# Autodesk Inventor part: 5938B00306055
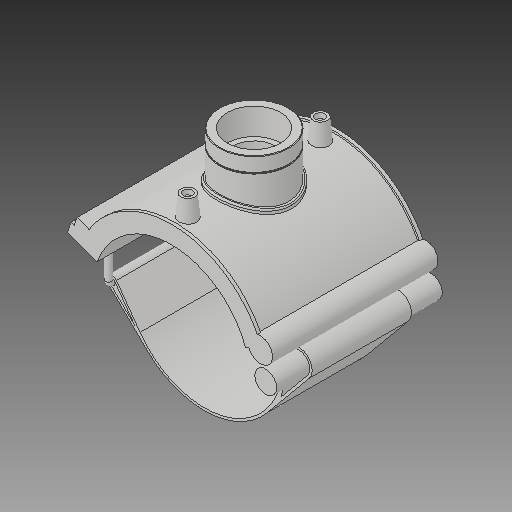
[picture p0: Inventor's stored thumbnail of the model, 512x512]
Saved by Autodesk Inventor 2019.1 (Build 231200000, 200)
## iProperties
Created: 2017-07
Part Number: 5938B00306055
Material: Generic
Description: PLASSON TRANSITION SADDLE 6''IPS x 2"NPT
Document SubType Name: Modeling
Designer: KIM
Density: 1 g/cm^3
Appearance: Default
Author: KIM
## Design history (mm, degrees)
derived "5938B.ipt"
feature "Solid1::5938B.ipt"
tag "TaggingFeature1"
body "Solid1"
other parameters: "d_" = 168, "B_" = 173.736, "H_" = 46.736, "L_" = 176.022, "d_t" = 6, "G_" = 56.656, "d148" = 2.52, "d160" = 2.52, "d169" = 2.52, "d192" = 6.72, "d0" = 168, "d1" = 201.6, "d2" = 434.34, "d3" = 42, "d4" = 176.022, "d5" = 0, "d40" = 104.832, "d41" = 79.3184, "d43" = 0, "d45" = 0, "d47" = 147.536, "d48" = 73.6528, "d50" = 0, "d78" = 122.8, "d79" = 15, "d80" = 70.4088, "d82" = 5 deg, "d84" = 4, "d85" = 14, "d86" = 0, "d87" = 3, "d88" = 0, "d96" = 205.632, "d97" = 3.52044, "d98" = 0, "d102" = 1.69968, "d103" = 56.656, "d104" = 28.0416, "d105" = 0, "d106" = 45.3248, "d108" = 0, "d109" = -15.57867, "d111" = 0.5, "d112" = 0.5, "d113" = 0, "d114" = 0.5, "d117" = 0.56656, "d120" = 140 deg, "d121" = 24.228, "d122" = 20 deg, "d123" = 806.4, "d124" = 120.96, "d126" = 0, "d143" = 173.04, "d145" = 25.84615, "d149" = 2.52, "d150" = 28.43077, "d153" = 176.022, "d154" = 0, "d156" = 100.8, "d157" = 160 deg, "d159" = 6.72, "d161" = 2.52, "d162" = 105.6132, "d163" = 0, "d164" = 84, "d167" = 16.8, "d168" = 98.34146, "d170" = 2.52, "d172" = 0, "d173" = 1, "d175" = 84, "d176" = 20 deg, "d177" = 11.76, "d178" = 33.6, "d180" = 0, "d183" = 13.44, "d184" = 9.408, "d185" = 57.20715, "d186" = 57.20715, "d187" = 100.8, "d188" = 10.08, "d189" = 11.76, "d190" = 0, "d191" = 120.96, "d193" = 6.72, "d194" = 3.444, "d195" = 90 deg, "d197" = 0, "d199" = 0
